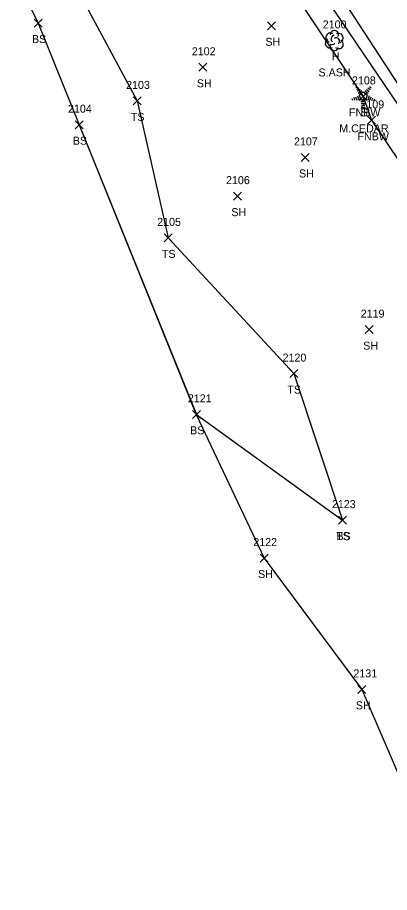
# Model space of a CAD drawing. Extents: x 1443590 to 1445966, y 578314 to 580556.
# Drawn here: x 1444746 to 1444839, y 579335.5 to 579554.1 of the extents above; entities that cross this region are included whole.
import ezdxf

# ---------------------------------------------------------------- set-up
doc = ezdxf.new("R2010")
doc.units = 0
for name, color, linetype in [('L_A', 7, 'Continuous'), ('L_C', 7, 'Continuous'), ('L_I', 7, 'Continuous'), ('L_TIC', 7, 'Continuous'), ('LELB', 7, 'Continuous'), ('LFNC', 7, 'Continuous'), ('LSOGP', 7, 'Continuous'), ('LTC', 7, 'Continuous'), ('LTD', 7, 'Continuous'), ('PET', 7, 'Continuous')]:
    doc.layers.add(name, color=color, linetype=linetype)

msp = doc.modelspace()

# ---------------------------------------------------------------- linework, layer by layer
at = {"layer": 'L_TIC'}
for points in [[(1444750.18, 579551.76), (1444752.18, 579553.76)], [(1444752.18, 579551.76), (1444750.18, 579553.76)], [(1444808.51, 579551.08), (1444810.51, 579553.08)], [(1444810.51, 579551.08), (1444808.51, 579553.08)], [(1444791.36, 579540.7), (1444793.36, 579542.7)], [(1444793.36, 579540.7), (1444791.36, 579542.7)], [(1444831.41, 579533.43), (1444833.41, 579535.43)], [(1444833.41, 579533.43), (1444831.41, 579535.43)], [(1444774.93, 579532.3), (1444776.93, 579534.3)], [(1444776.93, 579532.3), (1444774.93, 579534.3)], [(1444760.39, 579526.36), (1444762.39, 579528.36)], [(1444762.39, 579526.36), (1444760.39, 579528.36)], [(1444833.53, 579527.45), (1444835.53, 579529.45)], [(1444835.53, 579527.45), (1444833.53, 579529.45)], [(1444816.91, 579518.17), (1444818.91, 579520.17)], [(1444818.91, 579518.17), (1444816.91, 579520.17)], [(1444799.98, 579508.5), (1444801.98, 579510.5)], [(1444801.98, 579508.5), (1444799.98, 579510.5)], [(1444782.7, 579498.07), (1444784.7, 579500.07)], [(1444784.7, 579498.07), (1444782.7, 579500.07)], [(1444832.97, 579475.14), (1444834.97, 579477.14)], [(1444834.97, 579475.14), (1444832.97, 579477.14)], [(1444814.07, 579464.15), (1444816.07, 579466.15)], [(1444816.07, 579464.15), (1444814.07, 579466.15)], [(1444789.73, 579453.97), (1444791.73, 579455.97)], [(1444791.73, 579453.97), (1444789.73, 579455.97)], [(1444826.31, 579427.54), (1444828.31, 579429.54)], [(1444828.31, 579427.54), (1444826.31, 579429.54)], [(1444826.31, 579427.54), (1444828.31, 579429.54)], [(1444828.31, 579427.54), (1444826.31, 579429.54)], [(1444806.67, 579418.05), (1444808.67, 579420.05)], [(1444808.67, 579418.05), (1444806.67, 579420.05)], [(1444831.13, 579385.23), (1444833.13, 579387.23)], [(1444833.13, 579385.23), (1444831.13, 579387.23)]]:
    msp.add_lwpolyline(points, dxfattribs=at)
at = {"layer": 'LELB'}
for points in [[(1444746.95, 579691.28), (1444754.81, 579677.63), (1444764.37, 579659.32), (1444774.71, 579638.31), (1444788.05, 579611.23), (1444796.2, 579597.8), (1444819.99, 579563.54), (1444841.2, 579532.22), (1444866.71, 579495.19), (1444887.95, 579464.21), (1444910.73, 579432.04), (1444934.76, 579396.06), (1444960.57, 579355.06), (1444979.05, 579324.01)], [(1444774.64, 579583.81), (1444761.81, 579559.57), (1444775.93, 579533.3), (1444783.7, 579499.07), (1444815.07, 579465.15), (1444827.31, 579428.54)], [(1444751.18, 579552.76), (1444761.39, 579527.36), (1444790.73, 579454.97), (1444827.31, 579428.54)]]:
    msp.add_lwpolyline(points, dxfattribs=at)
at = {"layer": 'LFNC'}
msp.add_lwpolyline([(1444791.16, 579595.89), (1444815.01, 579560.49), (1444832.41, 579534.43), (1444834.53, 579528.45), (1444859.99, 579490.71), (1444879.37, 579461.24), (1444905.02, 579419.83), (1444929.74, 579384.21), (1444938.64, 579368.28), (1444958.45, 579336.73), (1444970.59, 579318.86)], dxfattribs=at)
at = {"layer": 'LSOGP'}
msp.add_lwpolyline([(1444746, 579563.39), (1444751.18, 579552.76), (1444761.39, 579527.36), (1444790.72, 579454.97), (1444807.67, 579419.05), (1444832.12, 579386.22), (1444847.54, 579350.44)], dxfattribs=at)
at = {"layer": 'LTC'}
for p, q in [((1444830.61, 579536.64), (1444830.96, 579536.9)), ((1444830.82, 579536.18), (1444831.34, 579536.56)), ((1444831.03, 579535.71), (1444831.73, 579536.22)), ((1444831.23, 579535.25), (1444832.11, 579535.88)), ((1444831.46, 579534.79), (1444832.47, 579535.53)), ((1444831.46, 579534.79), (1444831.85, 579533.6)), ((1444832.47, 579535.53), (1444833.47, 579534.8)), ((1444832.89, 579535.84), (1444833.7, 579535.25)), ((1444833.47, 579534.8), (1444833.08, 579533.6)), ((1444833.26, 579536.19), (1444833.94, 579535.69)), ((1444833.63, 579536.53), (1444834.18, 579536.14)), ((1444834, 579536.88), (1444834.42, 579536.58)), ((1444829.64, 579533.92), (1444829.79, 579533.45)), ((1444830.09, 579534.14), (1444830.31, 579533.49)), ((1444830.55, 579534.36), (1444830.82, 579533.52)), ((1444831, 579534.57), (1444831.34, 579533.55)), ((1444833.08, 579533.6), (1444831.85, 579533.6)), ((1444833.04, 579533.1), (1444831.89, 579533.1)), ((1444832.95, 579532.6), (1444831.97, 579532.6)), ((1444833.91, 579534.53), (1444833.57, 579533.49)), ((1444834.35, 579534.28), (1444834.06, 579533.39)), ((1444834.79, 579534.03), (1444834.56, 579533.3)), ((1444835.24, 579533.78), (1444835.05, 579533.2)), ((1444832.87, 579532.1), (1444832.04, 579532.1)), ((1444832.79, 579531.6), (1444832.11, 579531.6))]:
    msp.add_line(p, q, dxfattribs=at)
at = {"layer": 'LTD'}
msp.add_line((1444825.2, 579548.42), (1444825.2, 579548.42), dxfattribs=at)
msp.add_line((1444825.2, 579548.42), (1444825.2, 579548.42), dxfattribs=at)
msp.add_arc((1444825.25, 579549.85), 1.05, 335.5272, 180.9563, dxfattribs=at)
for centre, major_axis, ratio, start_param, end_param in [((1444824.41, 579549.08), (1.21, -0.51), 0.895232, 1.570796, 4.712389), ((1444826.24, 579549), (-1.14, -0.48), 0.949671, 1.570796, 4.712389), ((1444824.12, 579547.71), (0.58, -1.04), 0.959034, 3.141593, 6.283185), ((1444824.99, 579548.88), (-0.208, -0.792), 0.645439, 3.141593, 6.283185), ((1444825.7, 579548.25), (-0.5, 0.667), 0.989748, 3.141593, 6.283185), ((1444826.2, 579547.58), (-1.09, 0.79), 0.841452, 1.570796, 4.712389), ((1444825.2, 579546.92), (0.26, 1.06), 0.942809, 1.570796, 4.712389), ((1444824.74, 579547.67), (-0.625, -0.083), 0.423636, 0, 3.141593)]:
    msp.add_ellipse(centre, major_axis=major_axis, ratio=ratio, start_param=start_param, end_param=end_param, dxfattribs=at)
at = {"layer": 'PET'}
msp.add_lwpolyline([(1444749.57, 579692.99), (1444767.18, 579659.68), (1444778.42, 579640.07), (1444792.21, 579615.83), (1444803.11, 579597.28), (1444822.86, 579565.6), (1444843.8, 579533.42), (1444869.08, 579496.25), (1444890.19, 579465.65), (1444913.09, 579433.16), (1444937.14, 579397.54), (1444963.6, 579356.94), (1444983.04, 579326.35), (1445006.82, 579289.13), (1445021.79, 579264.22), (1445044.58, 579229.01), (1445059.66, 579205.24), (1445081.95, 579172.07), (1445091.01, 579154.93), (1445104.63, 579132.07), (1445107.77, 579117.84), (1445102.26, 579109.52), (1445094.76, 579101.93)], dxfattribs=at)

# ---------------------------------------------------------------- texts
at = {"layer": 'L_A'}
for s, p in [('BS', (1444749.62, 579547.76)), ('SH', (1444808, 579547.08)), ('H', (1444824.63, 579543.42)), ('SH', (1444790.85, 579536.7)), ('FNBW', (1444828.88, 579529.43)), ('S', (1444831.8, 579529.43)), ('TS', (1444774.34, 579528.3)), ('BS', (1444759.83, 579522.36)), ('FNBW', (1444831.01, 579523.45)), ('SH', (1444816.4, 579514.17)), ('SH', (1444799.47, 579504.5)), ('TS', (1444782.11, 579494.07)), ('SH', (1444832.45, 579471.14)), ('TS', (1444813.48, 579460.15)), ('BS', (1444789.17, 579449.97)), ('TS', (1444825.72, 579423.54)), ('BS', (1444825.75, 579423.54)), ('SH', (1444806.15, 579414.05)), ('SH', (1444830.61, 579381.23))]:
    msp.add_text(s, height=2, dxfattribs=at).set_placement(p)
at = {"layer": 'L_C'}
for s, p in [('S.ASH', (1444821.28, 579539.42)), ('M.CEDAR', (1444826.47, 579525.43))]:
    msp.add_text(s, height=2, dxfattribs=at).set_placement(p)
at = {"layer": 'L_I'}
for s, p in [('2100', (1444822.34, 579551.42)), ('2102', (1444789.59, 579544.7)), ('2108', (1444829.64, 579537.43)), ('2108', (1444829.64, 579537.43)), ('2103', (1444773.16, 579536.3)), ('2109', (1444831.75, 579531.45)), ('2104', (1444758.62, 579530.36)), ('2107', (1444815.14, 579522.17)), ('2106', (1444798.15, 579512.5)), ('2105', (1444780.93, 579502.07)), ('2119', (1444831.83, 579479.14)), ('2120', (1444812.29, 579468.15)), ('2121', (1444788.6, 579457.97)), ('2123', (1444824.62, 579431.54)), ('2123', (1444824.62, 579431.54)), ('2122', (1444804.97, 579422.05)), ('2131', (1444830, 579389.23))]:
    msp.add_text(s, height=2, dxfattribs=at).set_placement(p)
at = {"layer": 'LTC'}
msp.add_text('.', height=1.04, rotation=270, dxfattribs=at).set_placement((1444832.35, 579534.54))

doc.saveas('drawing.dxf')
